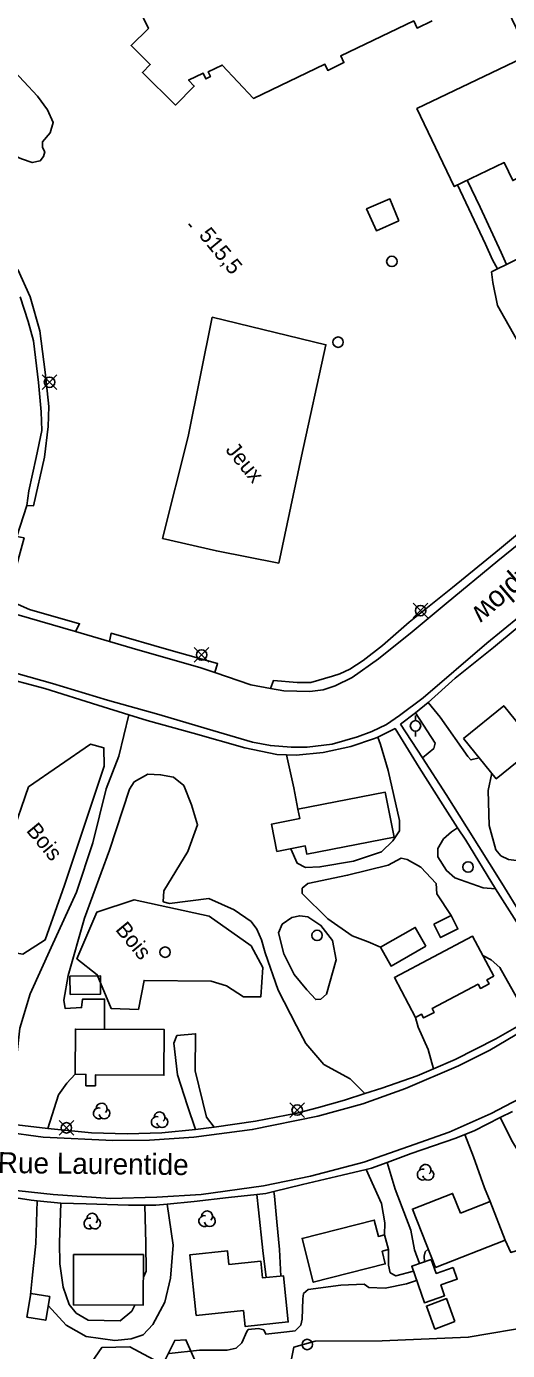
# Model space of a CAD drawing. Extents: x 347312 to 350503, y 6073086 to 6076432.
# Drawn here: x 348771.6 to 348863.8, y 6074362 to 6074615.9 of the extents above; entities that cross this region are included whole.
import ezdxf

# ---------------------------------------------------------------- set-up
doc = ezdxf.new("R2010")
doc.units = 0
for name, color, linetype in [('Level 19', 7, 'Continuous'), ('Level 2', 7, 'Continuous'), ('Level 21', 7, 'Continuous'), ('Level 22', 7, 'Continuous'), ('Level 3', 7, 'Continuous'), ('Level 31', 7, 'Continuous'), ('Level 36', 7, 'Continuous'), ('Level 37', 7, 'Continuous'), ('Level 44', 7, 'Continuous'), ('Level 56', 7, 'Continuous')]:
    doc.layers.add(name, color=color, linetype=linetype)

msp = doc.modelspace()

# ---------------------------------------------------------------- linework, layer by layer
at = {"layer": 'Level 19'}
for points in [[(348918.43, 6074592.55), (348916.87, 6074591.16), (348913.79, 6074589.18), (348905.77, 6074585.31), (348895.82, 6074580.42), (348886, 6074575.72), (348884.53, 6074575.24), (348884.25, 6074575.76), (348882.54, 6074578.9), (348882.36, 6074579.23), (348867.9, 6074572.37), (348863.63, 6074570.27), (348861.9, 6074569.42), (348860.77, 6074568.86)], [(348918.32, 6074581.42), (348916.79, 6074581.35), (348916.43, 6074581.33), (348909.29, 6074578.2), (348898.12, 6074572.88), (348888.78, 6074568.43), (348888.27, 6074567.77), (348890.29, 6074563.42), (348880.91, 6074559.01), (348868.35, 6074553.21), (348867.86, 6074554.16), (348865.56, 6074555.96), (348861.88, 6074562.38), (348861.01, 6074566.78), (348860.77, 6074568.86)], [(348858.39, 6074475.66), (348856.8, 6074475.23), (348856.25, 6074475.9), (348850.92, 6074483.43), (348848.64, 6074486.28)], [(348767.61, 6074405.52), (348768.93, 6074410.7), (348769.75, 6074418.56), (348770.34, 6074423.81), (348772.31, 6074430.38), (348776.32, 6074439.27), (348781.18, 6074449.85), (348784.3, 6074459.35), (348786.9, 6074469.69), (348789.29, 6074475.94), (348791.24, 6074483.88)], [(348846.21, 6074484.25), (348849.94, 6074478.47), (348849.73, 6074477.46), (348847.54, 6074475.62)], [(348838.96, 6074479.63), (348839.5, 6074478.19), (348840.93, 6074473.21), (348843.09, 6074463.63), (348843.12, 6074461.61), (348841.85, 6074459.71), (348839.66, 6074457.64), (348834.28, 6074455.83), (348827.86, 6074454.73), (348825.11, 6074454.61), (348823.47, 6074455.42), (348822.29, 6074458.2)], [(348821.46, 6074476.21), (348822.86, 6074469.91), (348823.66, 6074465.78)], [(348786.58, 6074423.58), (348786.58, 6074429.36), (348782.34, 6074429.33), (348782.16, 6074427.75), (348779.03, 6074427.54), (348778.78, 6074429.14), (348779.59, 6074433.92), (348782.76, 6074444.9), (348787.55, 6074457.92), (348791.33, 6074469.63), (348792.27, 6074471.02), (348794.85, 6074472.52), (348797.33, 6074472.41), (348799.82, 6074471.94), (348801.76, 6074470.32), (348803.27, 6074466.6), (348804.4, 6074462.8), (348802.51, 6074457.66), (348797.97, 6074450.13), (348797.82, 6074448.05), (348799.01, 6074447.69), (348806.57, 6074448.69), (348811.4, 6074446.48), (348814.67, 6074444.25), (348815.8, 6074442.79), (348816.68, 6074440.71), (348817.36, 6074438.27), (348819.86, 6074431.09), (348823.37, 6074424.23), (348825.15, 6074420.82), (348828.63, 6074416.8), (348833.68, 6074414.04), (348836.45, 6074411.24)], [(348903.21, 6074452.61), (348898.9, 6074457.29), (348893.63, 6074463.12), (348887.95, 6074467.63), (348883.19, 6074464.98), (348879.98, 6074463.79), (348874.86, 6074461.22), (348872.05, 6074459.46), (348865.53, 6074455.94), (348864.04, 6074456.12), (348862.55, 6074456.83), (348861.59, 6074457.99), (348860.3, 6074462.63), (348860.12, 6074469.35), (348860.79, 6074472.71)], [(348861.52, 6074450.49), (348859.17, 6074450.7), (348853.75, 6074452.64), (348852.16, 6074454.02), (348850.48, 6074456.68), (348850.46, 6074458.25), (348851.56, 6074460.08), (348853.11, 6074461.46), (348854.27, 6074462.21)], [(348839.45, 6074439.3), (348837.09, 6074440.33), (348834.05, 6074441.48), (348829.37, 6074444.78), (348824.49, 6074449.59), (348824.46, 6074450.62), (348825.52, 6074451.51), (348833.17, 6074453.11), (348840.93, 6074455.04), (348843.41, 6074456.37), (348844.58, 6074456.14), (348847.22, 6074454.67), (348850.12, 6074451.52), (348850.27, 6074449.54), (348853.03, 6074445.4)], [(348819.9, 6074442.06), (348820.97, 6074438.06), (348822.9, 6074434.1), (348825.34, 6074431.16), (348827.05, 6074429.28), (348828.03, 6074429.36), (348829.1, 6074430.33), (348830.99, 6074436.9), (348830.26, 6074440.59), (348828.07, 6074443.5), (348825.52, 6074445.13), (348823.99, 6074445.35), (348822.49, 6074445), (348820.62, 6074443.73), (348819.9, 6074442.06)], [(348859.09, 6074437.7), (348860.72, 6074436.92), (348862.34, 6074435.42), (348865.54, 6074429.74), (348867.91, 6074425.47)], [(348849.64, 6074415.96), (348848.59, 6074419.68), (348846.69, 6074423.96), (348846.18, 6074425.85)], [(348807.62, 6074404.77), (348806.13, 6074406.75), (348803.94, 6074415.62), (348804.04, 6074422.73), (348800.45, 6074422.36), (348799.87, 6074420.89), (348800.56, 6074414.82), (348802.48, 6074408.89), (348803.98, 6074404.38)], [(348775.69, 6074404.54), (348777.73, 6074411.01), (348779.36, 6074413.21), (348780.94, 6074414.95)], [(348862.44, 6074406.64), (348864.77, 6074401.98), (348867.83, 6074396.93), (348869.51, 6074394.22), (348871.74, 6074390.98), (348874.29, 6074390.25), (348876.14, 6074390.45), (348880.77, 6074392.99), (348884.26, 6074395.02), (348887.82, 6074398.4), (348892.52, 6074402.19)], [(348855.65, 6074403.38), (348857.28, 6074399.13), (348859.4, 6074393.15), (348860.49, 6074390.53)], [(348840.26, 6074384.16), (348840.3, 6074386.46), (348839.69, 6074390.17), (348836.71, 6074396.68)], [(348840.74, 6074398.03), (348842.27, 6074392.94), (348845.31, 6074385.02), (348845.99, 6074381.3), (348846.97, 6074378.65)], [(348863.39, 6074383.13), (348864.44, 6074380.78), (348872.91, 6074383.38), (348880.53, 6074386.47), (348888.2, 6074391.12), (348893.71, 6074395.3), (348896.39, 6074397.4)], [(348773.66, 6074390.68), (348773.38, 6074382.52), (348772.71, 6074375.84), (348772.41, 6074372.63)], [(348815.76, 6074391.91), (348816.08, 6074388.93), (348816.89, 6074381.17), (348817.57, 6074375.95)], [(348820.37, 6074376.24), (348820.14, 6074381.35), (348819.6, 6074386.64), (348819.18, 6074391.57), (348819.04, 6074392.49)], [(348775.77, 6074370.58), (348779.19, 6074366.82), (348783.08, 6074364.66), (348788.52, 6074363.88), (348791.65, 6074364.18), (348793.96, 6074364.99), (348795.85, 6074366.96), (348798.15, 6074371.23), (348799.21, 6074375.82), (348799.73, 6074382.14), (348798.61, 6074390.04)], [(348778.18, 6074390.21), (348777.92, 6074382.67), (348777.97, 6074378.56), (348778.67, 6074374.1), (348779.77, 6074370.79), (348781.13, 6074369.15), (348783.46, 6074367.79), (348789.57, 6074367.65), (348791.78, 6074369.5), (348792.41, 6074370.69)], [(348794.31, 6074389.82), (348794.51, 6074382.52), (348794.55, 6074377.16), (348794.01, 6074376.03)], [(348845.78, 6074377.21), (348842.44, 6074376.28), (348841.35, 6074376.87), (348841.03, 6074378.34), (348840.98, 6074381.32)]]:
    msp.add_lwpolyline(points, dxfattribs=at)
at = {"layer": 'Level 2'}
for points in [[(348773.71, 6074602.54), (348775.66, 6074599.9), (348776.75, 6074597.49), (348776.15, 6074595.51), (348774.7, 6074593.76), (348774.68, 6074592.67), (348775.12, 6074591.84), (348774.9, 6074590.99), (348774.25, 6074590.17), (348772.7, 6074589.81), (348770.66, 6074590.5), (348765.57, 6074592.77), (348759.36, 6074596.37), (348754.44, 6074598.91), (348747.99, 6074602.32), (348741.38, 6074606.24), (348736.37, 6074609.52), (348732.09, 6074612.88), (348727.52, 6074617.06), (348724.82, 6074619.44)], [(348763.31, 6074613.78), (348763.77, 6074613.06), (348768.47, 6074608.16), (348768.47, 6074608.16), (348773.71, 6074602.54)], [(348860.74, 6074389.88), (348860.72, 6074389.87)], [(348848.62, 6074381.4), (348848.05, 6074380.89), (348847.83, 6074380.04), (348847.91, 6074378.98)], [(348846.4, 6074375.42), (348844.48, 6074374.77), (348840.37, 6074373.95), (348837.26, 6074374.08), (348836.37, 6074374.67), (348831.87, 6074374.49), (348825.64, 6074373.66), (348824.7, 6074372.87), (348824.62, 6074371.86), (348824.43, 6074367.96), (348824.19, 6074366.82), (348823.09, 6074365.76), (348821.55, 6074365.53), (348817.52, 6074365.09), (348817.09, 6074365.92), (348816.09, 6074366.16), (348814.12, 6074365.97), (348813.88, 6074365.63), (348812.9, 6074363.46), (348811.79, 6074362.4), (348810.1, 6074362.04), (348804.8, 6074362), (348798.95, 6074361.36)]]:
    msp.add_lwpolyline(points, dxfattribs=at)
at = {"layer": 'Level 21'}
for points in [[(348845.52, 6074499.78), (348852.09, 6074505.23), (348862, 6074513.43), (348873.72, 6074522.98), (348880.83, 6074528.95), (348888.26, 6074534.9), (348898.13, 6074543.43), (348901.49, 6074546.79), (348904.7, 6074550.25), (348907.86, 6074554.12), (348910.43, 6074557.71), (348912.96, 6074562.72), (348915.75, 6074570.58), (348918.32, 6074581.42), (348918.55, 6074591.77), (348918.43, 6074592.55), (348917.45, 6074599.02), (348916.4, 6074604.19), (348915.12, 6074608.11), (348912.56, 6074614.21), (348908.42, 6074623.14)], [(348770.41, 6074564.04), (348771.96, 6074559.36), (348772.97, 6074555.6), (348773.94, 6074547.64), (348774.42, 6074541.99), (348774.52, 6074538.43), (348773.44, 6074533.22), (348772.06, 6074526.83), (348771.69, 6074524.03), (348769.78, 6074518.09)], [(348869.26, 6074505.31), (348859.88, 6074497.64), (348847.67, 6074487.15), (348843.13, 6074483.78), (348840.6, 6074482.04), (348837.83, 6074480.69), (348835.08, 6074479.66), (348830.18, 6074478.26), (348825.4, 6074477.71), (348822.33, 6074477.7), (348818.36, 6074477.98), (348814.95, 6074478.67), (348806.27, 6074481.19), (348796.96, 6074483.94), (348787.11, 6074486.69), (348776.57, 6074489.92), (348765.4, 6074493.01)], [(348769.76, 6074503.11), (348780.99, 6074499.86), (348787.54, 6074497.93), (348792.98, 6074496.33), (348804.81, 6074492.98), (348807.7, 6074491.99), (348814.6, 6074489.65), (348818.42, 6074488.95), (348820.95, 6074488.49), (348825.92, 6074488.36), (348828.48, 6074488.7), (348830.76, 6074489.48), (348834.04, 6074491.04), (348839.09, 6074494.61), (348845.52, 6074499.78)], [(348767.35, 6074403.9), (348774.78, 6074402.9), (348788.15, 6074402.22), (348795.17, 6074402.32), (348803.67, 6074402.9), (348814.9, 6074404.35), (348827.45, 6074406.91), (348836.06, 6074409.25), (348844.24, 6074412.21), (348854.42, 6074416.55), (348860.44, 6074419.58), (348870.13, 6074425.31)], [(348767.86, 6074392.86), (348776.75, 6074391.88), (348787.7, 6074391.14), (348796.58, 6074391.36), (348805.12, 6074391.9), (348817.06, 6074393.57), (348826.08, 6074395.43), (348836.27, 6074398.12), (348844.82, 6074401.08), (348852.65, 6074403.82), (348860.72, 6074407.45), (348870.22, 6074412.42)]]:
    msp.add_lwpolyline(points, dxfattribs=at)
at = {"layer": 'Level 22'}
for points in [[(348863.63, 6074570.27), (348862.62, 6074572.59), (348858.61, 6074581.25), (348856.11, 6074586.41)], [(348854.24, 6074585.51), (348859.59, 6074574.13), (348860.92, 6074571.16), (348861.9, 6074569.42)], [(348916.79, 6074581.35), (348915.12, 6074574.33), (348913.61, 6074569.35), (348910.94, 6074562.34), (348907.1, 6074555.94), (348903.64, 6074551.52), (348899.23, 6074546.52), (348894.88, 6074542.64), (348891.75, 6074540), (348884.78, 6074534.21), (348878.27, 6074528.96), (348872.31, 6074524.03), (348862.26, 6074515.65), (348853.27, 6074508.32), (348844.96, 6074501.63), (348839.87, 6074497.19), (348836.14, 6074494.28), (348833.59, 6074492.66), (348831.71, 6074491.77), (348830.28, 6074491.32), (348826.13, 6074490.1), (348823.52, 6074490.09), (348818.94, 6074490.47), (348818.42, 6074488.95)], [(348771.69, 6074524.03), (348772.95, 6074523.95), (348775.04, 6074533.28), (348775.77, 6074539.18), (348775.87, 6074543.05), (348775.18, 6074549.58), (348774.16, 6074557.51), (348772.29, 6074564.03), (348769.97, 6074569.27)], [(348780.99, 6074499.86), (348781.78, 6074501.35), (348772.17, 6074504.08), (348769.46, 6074505.28), (348768.52, 6074506.15), (348768.05, 6074506.89), (348768.97, 6074509.86), (348771.14, 6074517.81), (348769.78, 6074518.09)], [(348869.86, 6074504), (348861.14, 6074496.82), (348853.8, 6074490.94), (348848.64, 6074486.28), (348846.21, 6074484.25), (348843.33, 6074482.11)], [(348787.54, 6074497.93), (348787.84, 6074499.54), (348798.88, 6074496.34), (348808.24, 6074493.71), (348807.7, 6074491.99)], [(348867.35, 6074441.36), (348861.52, 6074450.49), (348855.82, 6074459.82), (348854.27, 6074462.21), (348851.41, 6074466.6), (348846.87, 6074473.8), (348842.27, 6074481.26), (348838.96, 6074479.63), (348838.34, 6074479.32), (348833.76, 6074477.8), (348828.47, 6074476.68), (348823.28, 6074476.17), (348821.46, 6074476.21), (348819.62, 6074476.26), (348813.45, 6074477.57), (348803.57, 6074480.36), (348797.31, 6074482.08), (348794.76, 6074482.78), (348791.24, 6074483.88), (348785.26, 6074485.75), (348775.12, 6074488.94), (348765.94, 6074491.35)], [(348843.33, 6074482.11), (348847.54, 6074475.62), (348852.05, 6074468.6), (348855.98, 6074462.39), (348862.73, 6074451.61), (348870.28, 6074439.32)], [(348767.61, 6074405.52), (348775.69, 6074404.54), (348784.07, 6074403.74), (348790.91, 6074403.53), (348797.57, 6074403.7), (348803.98, 6074404.38), (348807.62, 6074404.77), (348815.53, 6074405.98), (348823.41, 6074407.48), (348827.59, 6074408.58), (348832.57, 6074409.98), (348836.45, 6074411.24), (348839.71, 6074412.29), (348846.53, 6074414.63), (348849.64, 6074415.96), (348853.82, 6074417.75), (348861.56, 6074421.77), (348866.54, 6074424.53)], [(348766.77, 6074391.69), (348772.52, 6074390.8), (348773.66, 6074390.68), (348778.18, 6074390.21), (348783.07, 6074390.09), (348791.17, 6074389.81), (348794.31, 6074389.82), (348796.39, 6074389.83), (348798.61, 6074390.04), (348803.76, 6074390.52), (348810.31, 6074391.28), (348815.76, 6074391.91), (348817.48, 6074392.11), (348819.04, 6074392.49), (348824.53, 6074393.81), (348832.11, 6074395.59), (348836.71, 6074396.68), (348837.73, 6074396.93), (348840.74, 6074398.03), (348845.37, 6074399.73), (348853.91, 6074402.69), (348855.65, 6074403.38), (348857.46, 6074404.1), (348862.44, 6074406.64), (348864.77, 6074407.83)]]:
    msp.add_lwpolyline(points, dxfattribs=at)
at = {"layer": 'Level 3'}
msp.add_line((348802.72, 6074578.06), (348803.23, 6074577.44), dxfattribs=at)
at = {"layer": 'Level 31'}
for points in [[(348882.86, 6074595.17), (348876.31, 6074591.86), (348873.39, 6074590.46), (348864.84, 6074586.36), (348863.19, 6074589.8), (348853.62, 6074585.21), (348846.46, 6074600.15), (348868.01, 6074610.47), (348861.41, 6074624.25)], [(348849.4, 6074617), (348846.49, 6074615.61), (348845.84, 6074616.98), (348831.86, 6074610.28), (348832.47, 6074609), (348829.36, 6074607.5), (348828.81, 6074608.66), (348815.15, 6074602.11), (348809.15, 6074608.51), (348809.15, 6074608.51), (348806.44, 6074607.22), (348806.88, 6074606.3), (348805.99, 6074605.87), (348805.46, 6074606.97), (348802.68, 6074605.63), (348803.78, 6074604.47), (348800.2, 6074600.84), (348793.84, 6074607.1), (348795.35, 6074608.63), (348791.66, 6074612.26), (348794.98, 6074615.52), (348794.98, 6074615.52), (348793.08, 6074619.5)], [(348855.38, 6074479.37), (348863.1, 6074485.64), (348869.39, 6074477.9), (348861.67, 6074471.63), (348855.38, 6074479.37)], [(348823.66, 6074465.78), (348840.4, 6074469.04), (348842.07, 6074460.44), (348825.35, 6074457.19), (348825.05, 6074458.74), (348819.61, 6074457.68), (348818.59, 6074462.92), (348824.01, 6074463.98), (348823.66, 6074465.78)], [(348849.71, 6074443.73), (348853.03, 6074445.4), (348854.33, 6074442.82), (348851, 6074441.15), (348849.71, 6074443.73)], [(348848.19, 6074439.52), (348841.5, 6074435.7), (348839.45, 6074439.3), (348846.14, 6074443.12), (348848.19, 6074439.52)], [(348861.19, 6074433.74), (348857.11, 6074441.44), (348842.13, 6074433.5), (348846.18, 6074425.85), (348847.37, 6074426.47), (348847.75, 6074425.74), (348849.77, 6074426.81), (348849.37, 6074427.54), (348858.19, 6074432.22), (348858.63, 6074431.4), (348860.3, 6074432.28), (348859.89, 6074433.05), (348861.19, 6074433.74)], [(348779.94, 6074433.77), (348785.77, 6074433.85), (348785.82, 6074430.33), (348779.99, 6074430.25), (348779.94, 6074433.77)], [(348782.98, 6074412.76), (348782.99, 6074414.93), (348780.94, 6074414.95), (348781, 6074423.62), (348798.01, 6074423.51), (348797.95, 6074414.76), (348784.84, 6074414.85), (348784.83, 6074412.75), (348782.98, 6074412.76)], [(348854.8, 6074388.3), (348860.49, 6074390.53), (348863.39, 6074383.13), (348850, 6074377.88), (348845.6, 6074389.1), (348853.3, 6074392.11), (348854.8, 6074388.3)], [(348839.77, 6074381.01), (348840.39, 6074378.56), (348826.59, 6074375.06), (348824.46, 6074383.47), (348838.28, 6074386.97), (348839.07, 6074383.86), (348840.26, 6074384.16), (348840.98, 6074381.32), (348839.77, 6074381.01)], [(348780.63, 6074380.39), (348794.02, 6074380.37), (348794, 6074370.68), (348780.61, 6074370.71), (348780.63, 6074380.39)], [(348813.21, 6074369.63), (348804.14, 6074368.69), (348802.93, 6074380.34), (348810.14, 6074381.09), (348810.41, 6074378.47), (348816.53, 6074379.1), (348816.87, 6074375.88), (348820.87, 6074376.29), (348821.78, 6074367.46), (348813.53, 6074366.6), (348813.21, 6074369.63)], [(348853.42, 6074377.87), (348854.19, 6074375.63), (348851.05, 6074374.55), (348851.77, 6074372.47), (348847.89, 6074371.13), (348845.46, 6074378.13), (348849.22, 6074379.43), (348850.15, 6074376.74), (348853.42, 6074377.87)], [(348776.06, 6074372.32), (348775.29, 6074367.76), (348771.69, 6074368.37), (348772.46, 6074372.93), (348776.06, 6074372.32)], [(348853.75, 6074367.5), (348849.92, 6074366.08), (348848.29, 6074370.49), (348852.12, 6074371.91), (348853.75, 6074367.5)]]:
    msp.add_lwpolyline(points, dxfattribs=at)
at = {"layer": 'Level 36'}
for p, q in [((348774.62, 6074546.27), (348777.44, 6074549.09)), ((348774.62, 6074549.09), (348777.44, 6074546.27)), ((348845.75, 6074502.46), (348848.57, 6074505.28)), ((348845.75, 6074505.28), (348848.57, 6074502.46)), ((348803.77, 6074493.96), (348806.59, 6074496.78)), ((348803.77, 6074496.78), (348806.59, 6074493.96)), ((348846.19, 6074483.76), (348846.19, 6074482.76)), ((348846.19, 6074479.76), (348846.19, 6074480.76)), ((348822.1, 6074406.67), (348824.92, 6074409.49)), ((348822.1, 6074409.49), (348824.92, 6074406.67)), ((348777.86, 6074403.26), (348780.68, 6074406.08)), ((348777.86, 6074406.08), (348780.68, 6074403.26))]:
    msp.add_line(p, q, dxfattribs=at)
for centre in [(348841.66, 6074570.85), (348831.35, 6074555.36), (348776.03, 6074547.68), (348847.16, 6074503.87), (348805.18, 6074495.37), (348846.19, 6074481.77), (348856.27, 6074454.7), (348827.32, 6074441.59), (348798.18, 6074438.37), (348823.51, 6074408.08), (348779.27, 6074404.67), (348825.43, 6074363.12)]:
    msp.add_circle(centre, 1, dxfattribs=at)
at = {"layer": 'Level 37'}
for points in [[(348843.02, 6074578.65), (348838.69, 6074576.74), (348836.82, 6074580.91), (348841.28, 6074582.84), (348843.02, 6074578.65)], [(348797.67, 6074517.72), (348802.59, 6074537.26), (348807.23, 6074560.13), (348829, 6074554.87), (348824.36, 6074533.53), (348819.97, 6074513), (348808.02, 6074515.33), (348797.67, 6074517.72)]]:
    msp.add_lwpolyline(points, dxfattribs=at)
at = {"layer": 'Level 44'}
for points in [[(348786.48, 6074474.07), (348778.9, 6074451.24), (348775.2, 6074440.72), (348770.88, 6074437.99), (348766.7, 6074438.7), (348763.64, 6074443.83), (348765.43, 6074448.36), (348768.6, 6074460.24), (348772, 6074470.05), (348783.91, 6074478.25), (348786.46, 6074477.53), (348786.48, 6074474.07)], [(348807, 6074432.78), (348794.14, 6074432.96), (348793.07, 6074427.39), (348787.86, 6074427.54), (348785.18, 6074434.03), (348781.29, 6074437.09), (348785.1, 6074446.04), (348792.25, 6074448.43), (348806.66, 6074445.3), (348814.71, 6074439.55), (348816.95, 6074435.4), (348816.53, 6074429.77), (348813.2, 6074429.83), (348809.96, 6074431.93), (348807, 6074432.78)], [(348821.08, 6074353.7), (348822.85, 6074362.59), (348826.95, 6074363.78), (348839.77, 6074363.85), (348856.3, 6074364.5), (348869.14, 6074366.7), (348884.31, 6074366.65), (348892.77, 6074365.63), (348899.61, 6074374.55), (348903.18, 6074378.9), (348905.07, 6074378.24), (348912.28, 6074365.19), (348924.29, 6074348.51)], [(348783.4, 6074358.66), (348786.03, 6074362.53), (348791.43, 6074362.7), (348797.74, 6074359.26), (348800.02, 6074363.9), (348802.16, 6074364.03), (348805.34, 6074356.76)]]:
    msp.add_lwpolyline(points, dxfattribs=at)
for centre, start, end in [((348785.49, 6074407.45), 76.8848, 299.5691), ((348786.01, 6074408.35), 314.0633, 179.7519), ((348786.54, 6074407.45), 192.2171, 59.6742), ((348796.59, 6074405.78), 76.8848, 299.5691), ((348797.11, 6074406.68), 314.0633, 179.7519), ((348797.64, 6074405.78), 192.2171, 59.6742), ((348847.58, 6074395.7), 76.8848, 299.5691), ((348848.1, 6074396.6), 314.0633, 179.7519), ((348848.63, 6074395.7), 192.2171, 59.6742), ((348784.21, 6074387.23), 314.0633, 179.7519), ((348806.23, 6074387.69), 314.0633, 179.7519), ((348783.69, 6074386.33), 76.8848, 299.5691), ((348784.74, 6074386.33), 192.2171, 59.6742), ((348805.71, 6074386.79), 76.8848, 299.5691), ((348806.76, 6074386.79), 192.2171, 59.6742)]:
    msp.add_arc(centre, 1.05, start, end, dxfattribs=at)

# ---------------------------------------------------------------- texts
at = {"layer": 'Level 21'}
for s, rotation, p in [('Rue Aplow', 220.6505, (348876.34, 6074520.74)), ('Rue Laurentide', 359.3385, (348766.1, 6074396.02))]:
    msp.add_text(s, height=4, rotation=rotation, dxfattribs=at).set_placement(p)
at = {"layer": 'Level 3'}
msp.add_text('515,5', height=3, rotation=309.5679, dxfattribs=at).set_placement((348804.53, 6074575.82))
at = {"layer": 'Level 44'}
for p in [(348771.44, 6074461.63), (348788.52, 6074442.65)]:
    msp.add_text('Bois', height=3, rotation=309.568, dxfattribs=at).set_placement(p)
at = {"layer": 'Level 56'}
msp.add_text('Jeux', height=3, rotation=309.568, dxfattribs=at).set_placement((348809.62, 6074534.64))

doc.saveas('drawing.dxf')
